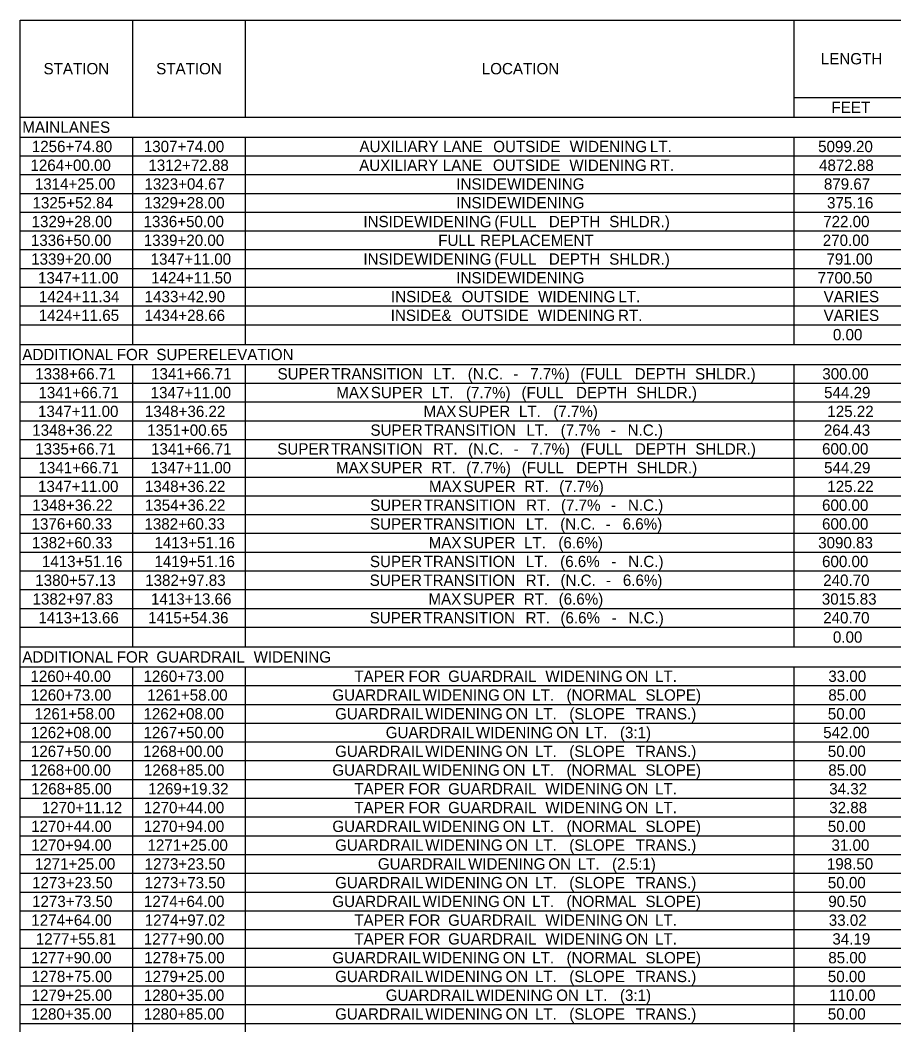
# Model space of a CAD drawing. Extents: x 1226590 to 1228573, y 151304 to 154224.
# Drawn here: x 1226590.3 to 1226976.1, y 153770.6 to 154214.4 of the extents above; entities that cross this region are included whole.
import ezdxf

# ---------------------------------------------------------------- set-up
doc = ezdxf.new("R2010")
doc.units = 0
doc.layers.add('R_Dimension', color=7, linetype='Continuous')

msp = doc.modelspace()

# ---------------------------------------------------------------- linework, layer by layer
at = {"layer": 'R_Dimension'}
for p, q in [((1226590.27, 154214.43), (1228572.93, 154214.43)), ((1226590.27, 152627.62), (1226590.27, 154214.43)), ((1226640, 154171.53), (1226640, 154214.43)), ((1226689.72, 154171.53), (1226689.72, 154214.43)), ((1226932.01, 154171.53), (1226932.01, 154214.43)), ((1226932.01, 154180.3), (1226981.73, 154180.3)), ((1226590.27, 154171.53), (1228572.93, 154171.53)), ((1226590.27, 154162.75), (1228572.93, 154162.75)), ((1226640, 154071.1), (1226640, 154162.75)), ((1226689.72, 154071.1), (1226689.72, 154162.75)), ((1226932.01, 154071.1), (1226932.01, 154162.75)), ((1226590.27, 154154.47), (1228572.93, 154154.47)), ((1226590.27, 154146.18), (1228572.93, 154146.18)), ((1226590.27, 154137.89), (1228572.93, 154137.89)), ((1226590.27, 154129.6), (1228572.93, 154129.6)), ((1226590.27, 154121.32), (1228572.93, 154121.32)), ((1226590.27, 154113.03), (1228572.93, 154113.03)), ((1226590.27, 154104.74), (1228572.93, 154104.74)), ((1226590.27, 154096.45), (1228572.93, 154096.45)), ((1226590.27, 154088.17), (1228572.93, 154088.17)), ((1226590.27, 154079.88), (1228572.93, 154079.88)), ((1226590.27, 154071.1), (1228572.93, 154071.1)), ((1226590.27, 154062.33), (1228572.93, 154062.33)), ((1226640, 153937.53), (1226640, 154062.33)), ((1226689.72, 153937.53), (1226689.72, 154062.33)), ((1226932.01, 153937.53), (1226932.01, 154062.33)), ((1226590.27, 154054.04), (1228572.93, 154054.04)), ((1226590.27, 154045.75), (1228572.93, 154045.75)), ((1226590.27, 154037.47), (1228572.93, 154037.47)), ((1226590.27, 154029.18), (1228572.93, 154029.18)), ((1226590.27, 154020.89), (1228572.93, 154020.89)), ((1226590.27, 154012.6), (1228572.93, 154012.6)), ((1226590.27, 154004.32), (1228572.93, 154004.32)), ((1226590.27, 153996.03), (1228572.93, 153996.03)), ((1226590.27, 153987.74), (1228572.93, 153987.74)), ((1226590.27, 153979.45), (1228572.93, 153979.45)), ((1226590.27, 153971.17), (1228572.93, 153971.17)), ((1226590.27, 153962.88), (1228572.93, 153962.88)), ((1226590.27, 153954.59), (1228572.93, 153954.59)), ((1226590.27, 153946.3), (1228572.93, 153946.3)), ((1226590.27, 153937.53), (1228572.93, 153937.53)), ((1226590.27, 153928.75), (1228572.93, 153928.75)), ((1226640, 153323.28), (1226640, 153928.75)), ((1226689.72, 153323.28), (1226689.72, 153928.75)), ((1226932.01, 153323.28), (1226932.01, 153928.75)), ((1226590.27, 153920.47), (1228572.93, 153920.47)), ((1226590.27, 153912.18), (1228572.93, 153912.18)), ((1226590.27, 153903.89), (1228572.93, 153903.89)), ((1226590.27, 153895.6), (1228572.93, 153895.6)), ((1226590.27, 153887.32), (1228572.93, 153887.32)), ((1226590.27, 153879.03), (1228572.93, 153879.03)), ((1226590.27, 153870.74), (1228572.93, 153870.74)), ((1226590.27, 153862.45), (1228572.93, 153862.45)), ((1226590.27, 153854.17), (1228572.93, 153854.17)), ((1226590.27, 153845.88), (1228572.93, 153845.88)), ((1226590.27, 153837.59), (1228572.93, 153837.59)), ((1226590.27, 153829.3), (1228572.93, 153829.3)), ((1226590.27, 153821.02), (1228572.93, 153821.02)), ((1226590.27, 153812.73), (1228572.93, 153812.73)), ((1226590.27, 153804.44), (1228572.93, 153804.44)), ((1226590.27, 153796.15), (1228572.93, 153796.15)), ((1226590.27, 153787.87), (1228572.93, 153787.87)), ((1226590.27, 153779.58), (1228572.93, 153779.58)), ((1226590.27, 153771.29), (1228572.93, 153771.29))]:
    msp.add_line(p, q, dxfattribs=at)

# ---------------------------------------------------------------- texts
for s, p in [('LENGTH', (1226943.8, 154194.87)), ('STATION', (1226600.62, 154190.48)), ('STATION', (1226650.35, 154190.48)), ('LOCATION', (1226794.11, 154190.48)), ('FEET', (1226948.5, 154173.42)), ('MAIN', (1226591.25, 154164.64)), (' LANES', (1226606.25, 154164.64)), ('1256+74.80', (1226595.43, 154156.11)), ('1307+74.00', (1226644.88, 154156.11)), ('AUXILIARY', (1226740.1, 154156.11)), (' LANE', (1226775.14, 154156.11)), (' OUTSIDE', (1226797.3, 154156.11)), (' WIDENING', (1226831.04, 154156.11)), (' LT.', (1226866.47, 154156.11)), ('5099.20', (1226942.6, 154156.11)), ('1264+00.00', (1226594.84, 154147.82)), ('1312+72.88', (1226646.9, 154147.82)), ('AUXILIARY', (1226739.98, 154147.82)), (' LANE', (1226775.02, 154147.82)), (' OUTSIDE', (1226797.18, 154147.82)), (' WIDENING', (1226830.92, 154147.82)), (' RT.', (1226866.36, 154147.82)), ('4872.88', (1226943.01, 154147.82)), ('1314+25.00', (1226596.77, 154139.54)), ('1323+04.67', (1226645.17, 154139.54)), ('INSIDE', (1226782.87, 154139.54)), (' WIDENING', (1226803.42, 154139.54)), ('879.67', (1226945.14, 154139.54)), ('1325+52.84', (1226595.76, 154131.25)), ('1329+28.00', (1226645.07, 154131.25)), ('INSIDE', (1226782.87, 154131.25)), (' WIDENING', (1226803.42, 154131.25)), ('375.16', (1226946.54, 154131.25)), ('1329+28.00', (1226595.35, 154122.96)), ('1336+50.00', (1226644.76, 154122.96)), ('INSIDE', (1226741.83, 154122.96)), (' WIDENING', (1226762.38, 154122.96)), (' (FULL', (1226797.81, 154122.96)), (' DEPTH', (1226821.87, 154122.96)), (' SHLDR.)', (1226848.52, 154122.96)), ('722.00', (1226944.84, 154122.96)), ('1336+50.00', (1226595.03, 154114.67)), ('1339+20.00', (1226644.88, 154114.67)), ('FULL', (1226774.88, 154114.67)), (' REPLACEMENT', (1226791.49, 154114.67)), ('270.00', (1226944.65, 154114.67)), ('1339+20.00', (1226595.15, 154106.39)), ('1347+11.00', (1226647.91, 154106.39)), ('INSIDE', (1226741.83, 154106.39)), (' WIDENING', (1226762.38, 154106.39)), (' (FULL', (1226797.81, 154106.39)), (' DEPTH', (1226821.87, 154106.39)), (' SHLDR.)', (1226848.52, 154106.39)), ('791.00', (1226946.26, 154106.39)), ('1347+11.00', (1226598.18, 154098.1)), ('1424+11.50', (1226648.11, 154098.1)), ('INSIDE', (1226782.87, 154098.1)), (' WIDENING', (1226803.42, 154098.1)), ('7700.50', (1226942.4, 154098.1)), ('1424+11.34', (1226598.6, 154089.81)), ('1433+42.90', (1226645.27, 154089.81)), ('INSIDE', (1226754.03, 154089.81)), (' &', (1226774.58, 154089.81)), (' OUTSIDE', (1226783.36, 154089.81)), (' WIDENING', (1226817.1, 154089.81)), (' LT.', (1226852.54, 154089.81)), ('VARIES', (1226945.02, 154089.81)), ('1424+11.65', (1226598.48, 154081.52)), ('1434+28.66', (1226645.23, 154081.52)), ('INSIDE', (1226753.92, 154081.52)), (' &', (1226774.47, 154081.52)), (' OUTSIDE', (1226783.25, 154081.52)), (' WIDENING', (1226816.99, 154081.52)), (' RT.', (1226852.42, 154081.52)), ('VARIES', (1226945.02, 154081.52)), ('0.00', (1226949.13, 154072.99)), ('ADDITIONAL', (1226591.25, 154064.22)), (' FOR', (1226631.09, 154064.22)), (' SUPERELEVATION', (1226648.57, 154064.22)), ('1338+66.71', (1226596.94, 154055.69)), ('1341+66.71', (1226648.09, 154055.69)), ('SUPER', (1226703.93, 154055.69)), (' TRANSITION', (1226725.79, 154055.69)), (' LT.', (1226770.9, 154055.69)), (' (N.C.', (1226786.06, 154055.69)), (' -', (1226806.18, 154055.69)), (' 7.7%)', (1226813.62, 154055.69)), (' (FULL', (1226835.71, 154055.69)), (' DEPTH', (1226859.76, 154055.69)), (' SHLDR.)', (1226886.42, 154055.69)), ('300.00', (1226944.45, 154055.69)), ('1341+66.71', (1226598.36, 154047.4)), ('1347+11.00', (1226647.91, 154047.4)), ('MAX', (1226729.86, 154047.4)), (' SUPER', (1226743.25, 154047.4)), (' LT.', (1226770.1, 154047.4)), (' (7.7%)', (1226785.25, 154047.4)), (' (FULL', (1226809.78, 154047.4)), (' DEPTH', (1226833.84, 154047.4)), (' SHLDR.)', (1226860.49, 154047.4)), ('544.29', (1226945.24, 154047.4)), ('1347+11.00', (1226598.18, 154039.11)), ('1348+36.22', (1226645.37, 154039.11)), ('MAX', (1226768.4, 154039.11)), (' SUPER', (1226781.79, 154039.11)), (' LT.', (1226808.64, 154039.11)), (' (7.7%)', (1226823.8, 154039.11)), ('125.22', (1226946.67, 154039.11)), ('1348+36.22', (1226595.64, 154030.82)), ('1351+00.65', (1226646.39, 154030.82)), ('SUPER', (1226744.96, 154030.82)), (' TRANSITION', (1226766.81, 154030.82)), (' LT.', (1226811.93, 154030.82)), (' (7.7%', (1226827.08, 154030.82)), (' N.C.)', (1226856.65, 154030.82)), ('264.43', (1226945.14, 154030.82)), (' -', (1226849.21, 154030.82)), ('1335+66.71', (1226596.94, 154022.54)), ('1341+66.71', (1226648.09, 154022.54)), ('SUPER', (1226703.82, 154022.54)), (' TRANSITION', (1226725.67, 154022.54)), (' RT.', (1226770.79, 154022.54)), (' (N.C.', (1226786.18, 154022.54)), (' 7.7%)', (1226813.74, 154022.54)), (' (FULL', (1226835.82, 154022.54)), (' DEPTH', (1226859.88, 154022.54)), (' SHLDR.)', (1226886.53, 154022.54)), ('600.00', (1226944.33, 154022.54)), (' -', (1226806.3, 154022.54)), ('1341+66.71', (1226598.36, 154014.25)), ('1347+11.00', (1226647.91, 154014.25)), ('MAX', (1226729.74, 154014.25)), (' SUPER', (1226743.13, 154014.25)), (' RT.', (1226769.98, 154014.25)), (' (7.7%)', (1226785.37, 154014.25)), (' (FULL', (1226809.9, 154014.25)), (' DEPTH', (1226833.95, 154014.25)), (' SHLDR.)', (1226860.61, 154014.25)), ('544.29', (1226945.24, 154014.25)), ('1347+11.00', (1226598.18, 154005.96)), ('1348+36.22', (1226645.37, 154005.96)), ('MAX', (1226770.79, 154005.96)), (' SUPER', (1226784.17, 154005.96)), (' RT.', (1226811.02, 154005.96)), (' (7.7%)', (1226826.42, 154005.96)), ('125.22', (1226946.67, 154005.96)), ('1348+36.22', (1226595.64, 153997.67)), ('1354+36.22', (1226645.37, 153997.67)), ('SUPER', (1226744.84, 153997.67)), (' TRANSITION', (1226766.69, 153997.67)), (' RT.', (1226811.81, 153997.67)), (' (7.7%', (1226827.2, 153997.67)), (' -', (1226849.33, 153997.67)), (' N.C.)', (1226856.77, 153997.67)), ('600.00', (1226944.33, 153997.67)), ('1376+60.33', (1226595.33, 153989.39)), ('1382+60.33', (1226645.17, 153989.39)), ('SUPER', (1226744.74, 153989.39)), (' TRANSITION', (1226766.59, 153989.39)), (' (N.C.', (1226826.87, 153989.39)), (' 6.6%)', (1226854.43, 153989.39)), ('600.00', (1226944.33, 153989.39)), (' LT.', (1226811.71, 153989.39)), (' -', (1226846.99, 153989.39)), ('1382+60.33', (1226595.45, 153981.1)), ('1413+51.16', (1226649.6, 153981.1)), ('MAX', (1226770.67, 153981.1)), (' SUPER', (1226784.05, 153981.1)), (' LT.', (1226810.9, 153981.1)), (' (6.6%)', (1226826.06, 153981.1)), ('3090.83', (1226942.62, 153981.1)), ('1413+51.16', (1226599.88, 153972.81)), ('1419+51.16', (1226649.6, 153972.81)), ('SUPER', (1226744.72, 153972.81)), (' TRANSITION', (1226766.57, 153972.81)), (' LT.', (1226811.69, 153972.81)), (' (6.6%', (1226826.85, 153972.81)), (' N.C.)', (1226856.89, 153972.81)), ('600.00', (1226944.33, 153972.81)), (' -', (1226849.45, 153972.81)), ('1380+57.13', (1226596.98, 153964.52)), ('1382+97.83', (1226645.49, 153964.52)), ('SUPER', (1226744.62, 153964.52)), (' TRANSITION', (1226766.47, 153964.52)), (' RT.', (1226811.59, 153964.52)), (' (N.C.', (1226826.99, 153964.52)), (' 6.6%)', (1226854.54, 153964.52)), ('240.70', (1226944.84, 153964.52)), (' -', (1226847.1, 153964.52)), ('1382+97.83', (1226595.76, 153956.24)), ('1413+13.66', (1226648.07, 153956.24)), ('MAX', (1226770.55, 153956.24)), (' SUPER', (1226783.93, 153956.24)), (' RT.', (1226810.79, 153956.24)), (' (6.6%)', (1226826.18, 153956.24)), ('3015.83', (1226944.23, 153956.24)), ('1413+13.66', (1226598.34, 153947.95)), ('1415+54.36', (1226646.77, 153947.95)), ('SUPER', (1226744.6, 153947.95)), (' TRANSITION', (1226766.45, 153947.95)), (' RT.', (1226811.57, 153947.95)), (' (6.6%', (1226826.97, 153947.95)), (' -', (1226849.56, 153947.95)), (' N.C.)', (1226857.01, 153947.95)), ('240.70', (1226944.84, 153947.95)), ('0.00', (1226949.13, 153939.42)), ('ADDITIONAL', (1226591.25, 153930.64)), (' FOR', (1226631.09, 153930.64)), (' GUARDRAIL', (1226648.57, 153930.64)), (' WIDENING', (1226691.52, 153930.64)), ('1260+40.00', (1226594.84, 153922.11)), ('1260+73.00', (1226644.76, 153922.11)), ('TAPER', (1226737.81, 153922.11)), (' FOR', (1226759.9, 153922.11)), (' GUARDRAIL', (1226777.38, 153922.11)), (' WIDENING', (1226820.33, 153922.11)), (' ON', (1226855.77, 153922.11)), (' LT.', (1226868.76, 153922.11)), ('33.00', (1226947.09, 153922.11)), (' (NORMAL', (1226829.66, 153913.82)), (' SLOPE)', (1226864.51, 153913.82)), ('1260+73.00', (1226595.03, 153913.82)), ('1261+58.00', (1226646.37, 153913.82)), ('GUARDRAIL', (1226728.13, 153913.82)), (' WIDENING', (1226766.08, 153913.82)), (' ON', (1226801.51, 153913.82)), (' LT.', (1226814.51, 153913.82)), ('85.00', (1226947.09, 153913.82)), ('1261+58.00', (1226596.65, 153905.54)), ('1262+08.00', (1226644.76, 153905.54)), ('GUARDRAIL', (1226729.35, 153905.54)), (' WIDENING', (1226767.3, 153905.54)), (' ON', (1226802.73, 153905.54)), (' LT.', (1226815.73, 153905.54)), (' (SLOPE', (1226830.88, 153905.54)), (' TRANS.)', (1226860.21, 153905.54)), ('50.00', (1226946.89, 153905.54)), ('1262+08.00', (1226595.03, 153897.25)), ('1267+50.00', (1226644.76, 153897.25)), ('GUARDRAIL', (1226751.69, 153897.25)), (' WIDENING', (1226789.64, 153897.25)), (' ON', (1226825.08, 153897.25)), (' LT.', (1226838.07, 153897.25)), (' (3:1)', (1226853.23, 153897.25)), ('542.00', (1226944.84, 153897.25)), ('1267+50.00', (1226595.03, 153888.96)), ('1268+00.00', (1226644.56, 153888.96)), ('GUARDRAIL', (1226729.35, 153888.96)), (' WIDENING', (1226767.3, 153888.96)), (' ON', (1226802.73, 153888.96)), (' LT.', (1226815.73, 153888.96)), (' (SLOPE', (1226830.88, 153888.96)), (' TRANS.)', (1226860.21, 153888.96)), ('50.00', (1226946.89, 153888.96)), ('1268+00.00', (1226594.84, 153880.67)), ('1268+85.00', (1226644.96, 153880.67)), ('GUARDRAIL', (1226728.13, 153880.67)), (' WIDENING', (1226766.08, 153880.67)), (' ON', (1226801.51, 153880.67)), (' LT.', (1226814.51, 153880.67)), (' (NORMAL', (1226829.66, 153880.67)), (' SLOPE)', (1226864.51, 153880.67)), ('85.00', (1226947.09, 153880.67)), ('1268+85.00', (1226595.23, 153872.39)), ('1269+19.32', (1226646.79, 153872.39)), ('TAPER', (1226737.81, 153872.39)), (' FOR', (1226759.9, 153872.39)), (' GUARDRAIL', (1226777.38, 153872.39)), (' WIDENING', (1226820.33, 153872.39)), (' ON', (1226855.77, 153872.39)), (' LT.', (1226868.76, 153872.39)), ('34.32', (1226947.5, 153872.39)), ('1270+11.12', (1226599.82, 153864.1)), ('1270+44.00', (1226644.88, 153864.1)), ('TAPER', (1226737.81, 153864.1)), (' FOR', (1226759.9, 153864.1)), (' GUARDRAIL', (1226777.38, 153864.1)), (' WIDENING', (1226820.33, 153864.1)), (' ON', (1226855.77, 153864.1)), (' LT.', (1226868.76, 153864.1)), ('32.88', (1226947.5, 153864.1)), ('1270+44.00', (1226595.15, 153855.81)), ('1270+94.00', (1226644.88, 153855.81)), ('GUARDRAIL', (1226728.13, 153855.81)), (' WIDENING', (1226766.08, 153855.81)), (' ON', (1226801.51, 153855.81)), (' LT.', (1226814.51, 153855.81)), (' (NORMAL', (1226829.66, 153855.81)), (' SLOPE)', (1226864.51, 153855.81)), ('50.00', (1226946.89, 153855.81)), ('1270+94.00', (1226595.15, 153847.52)), ('1271+25.00', (1226646.49, 153847.52)), ('GUARDRAIL', (1226729.35, 153847.52)), (' WIDENING', (1226767.3, 153847.52)), (' ON', (1226802.73, 153847.52)), (' LT.', (1226815.73, 153847.52)), (' (SLOPE', (1226830.88, 153847.52)), (' TRANS.)', (1226860.21, 153847.52)), ('31.00', (1226948.5, 153847.52)), ('1271+25.00', (1226596.77, 153839.24)), ('1273+23.50', (1226645.27, 153839.24)), ('GUARDRAIL', (1226748.23, 153839.24)), (' WIDENING', (1226786.18, 153839.24)), (' ON', (1226821.61, 153839.24)), (' LT.', (1226834.6, 153839.24)), (' (2.5:1)', (1226849.76, 153839.24)), ('198.50', (1226946.46, 153839.24)), ('1273+23.50', (1226595.55, 153830.95)), ('1273+73.50', (1226645.27, 153830.95)), ('GUARDRAIL', (1226729.35, 153830.95)), (' WIDENING', (1226767.3, 153830.95)), (' ON', (1226802.73, 153830.95)), (' LT.', (1226815.73, 153830.95)), (' (SLOPE', (1226830.88, 153830.95)), (' TRANS.)', (1226860.21, 153830.95)), ('50.00', (1226946.89, 153830.95)), ('1273+73.50', (1226595.55, 153822.66)), ('1274+64.00', (1226644.96, 153822.66)), ('GUARDRAIL', (1226728.13, 153822.66)), (' WIDENING', (1226766.08, 153822.66)), (' ON', (1226801.51, 153822.66)), (' LT.', (1226814.51, 153822.66)), (' (NORMAL', (1226829.66, 153822.66)), (' SLOPE)', (1226864.51, 153822.66)), ('90.50', (1226947.09, 153822.66)), ('1274+64.00', (1226595.23, 153814.37)), ('1274+97.02', (1226645.29, 153814.37)), ('TAPER', (1226737.81, 153814.37)), (' FOR', (1226759.9, 153814.37)), (' GUARDRAIL', (1226777.38, 153814.37)), (' WIDENING', (1226820.33, 153814.37)), (' ON', (1226855.77, 153814.37)), (' LT.', (1226868.76, 153814.37)), ('33.02', (1226947.3, 153814.37)), ('1277+55.81', (1226597.18, 153806.09)), ('1277+90.00', (1226644.88, 153806.09)), ('TAPER', (1226737.81, 153806.09)), (' FOR', (1226759.9, 153806.09)), (' GUARDRAIL', (1226777.38, 153806.09)), (' WIDENING', (1226820.33, 153806.09)), (' ON', (1226855.77, 153806.09)), (' LT.', (1226868.76, 153806.09)), ('34.19', (1226948.9, 153806.09)), ('1277+90.00', (1226595.15, 153797.8)), ('1278+75.00', (1226645.07, 153797.8)), ('GUARDRAIL', (1226728.13, 153797.8)), (' WIDENING', (1226766.08, 153797.8)), (' ON', (1226801.51, 153797.8)), (' LT.', (1226814.51, 153797.8)), (' (NORMAL', (1226829.66, 153797.8)), (' SLOPE)', (1226864.51, 153797.8)), ('85.00', (1226947.09, 153797.8)), (' (SLOPE', (1226830.88, 153789.51)), (' TRANS.)', (1226860.21, 153789.51)), ('1278+75.00', (1226595.35, 153789.51)), ('1279+25.00', (1226645.07, 153789.51)), ('GUARDRAIL', (1226729.35, 153789.51)), (' WIDENING', (1226767.3, 153789.51)), (' ON', (1226802.73, 153789.51)), (' LT.', (1226815.73, 153789.51)), ('50.00', (1226946.89, 153789.51)), ('1279+25.00', (1226595.35, 153781.22)), ('1280+35.00', (1226644.88, 153781.22)), ('GUARDRAIL', (1226751.69, 153781.22)), (' WIDENING', (1226789.64, 153781.22)), (' ON', (1226825.08, 153781.22)), (' LT.', (1226838.07, 153781.22)), (' (3:1)', (1226853.23, 153781.22)), ('110.00', (1226947.48, 153781.22)), ('1280+35.00', (1226595.15, 153772.94)), ('1280+85.00', (1226644.88, 153772.94)), ('GUARDRAIL', (1226729.35, 153772.94)), (' WIDENING', (1226767.3, 153772.94)), (' ON', (1226802.73, 153772.94)), (' LT.', (1226815.73, 153772.94)), (' (SLOPE', (1226830.88, 153772.94)), (' TRANS.)', (1226860.21, 153772.94)), ('50.00', (1226946.89, 153772.94))]:
    msp.add_text(s, height=5, dxfattribs=at).set_placement(p)

doc.saveas('drawing.dxf')
